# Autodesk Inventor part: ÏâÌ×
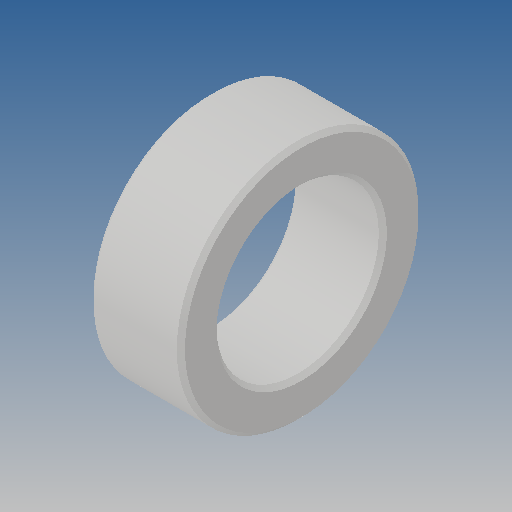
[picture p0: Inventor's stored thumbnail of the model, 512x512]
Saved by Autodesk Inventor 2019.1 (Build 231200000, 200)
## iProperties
Created: 2012-10
Part Number: ÏâÌ×
Material: Ogólny
Document SubType Name: Modeling
Designer: CADENGINEERING4
Density: 1 g/cm^3
Appearance: Domyślna
Author: CADENGINEERING4
Revision Number: ÈÎºÎ
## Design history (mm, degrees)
feature "Ðý×ª1"
node "Bryła1"
